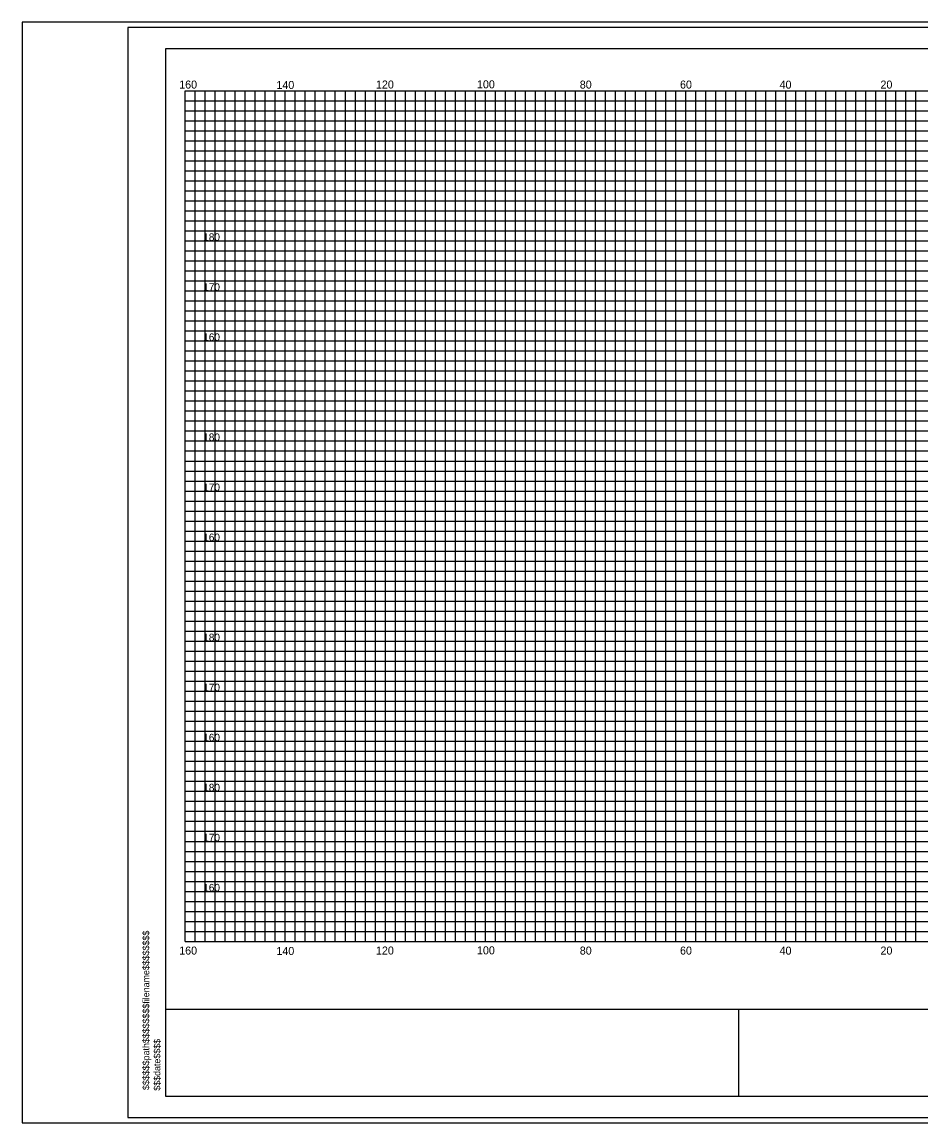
# Model space of a CAD drawing. Extents: x 967 to 1326, y 964 to 2864.
# Drawn here: x 967.4 to 1147, y 1523.7 to 1743.7 of the extents above; entities that cross this region are included whole.
import ezdxf

# ---------------------------------------------------------------- set-up
doc = ezdxf.new("R2010")
doc.units = 0
for name, color, linetype in [('Default', 7, 'Continuous'), ('RD_EX_RW', 7, 'Continuous'), ('RD_PD_Final_TX', 7, 'Continuous'), ('RD_SHT_ShtClip', 7, 'Continuous'), ('RD_XS_TX_Elev_PR', 7, 'Continuous'), ('RD_XS_TX_Slope', 7, 'Continuous')]:
    doc.layers.add(name, color=color, linetype=linetype)

msp = doc.modelspace()

# ---------------------------------------------------------------- linework, layer by layer
at = {"layer": 'RD_EX_RW'}
for p, q in [((1000, 1730), (1320, 1730)), ((1000, 1560), (1000, 1730)), ((1010, 1560), (1010, 1730)), ((1020, 1560), (1020, 1730)), ((1030, 1560), (1030, 1730)), ((1040, 1560), (1040, 1730)), ((1050, 1560), (1050, 1730)), ((1060, 1560), (1060, 1730)), ((1070, 1560), (1070, 1730)), ((1080, 1560), (1080, 1730)), ((1090, 1560), (1090, 1730)), ((1100, 1560), (1100, 1730)), ((1110, 1560), (1110, 1730)), ((1120, 1560), (1120, 1730)), ((1130, 1560), (1130, 1730)), ((1140, 1560), (1140, 1730)), ((1000, 1720), (1320, 1720)), ((1000, 1710), (1320, 1710)), ((1000, 1700), (1320, 1700)), ((1000, 1690), (1320, 1690)), ((1000, 1680), (1320, 1680)), ((1000, 1670), (1320, 1670)), ((1000, 1660), (1320, 1660)), ((1000, 1650), (1320, 1650)), ((1000, 1640), (1320, 1640)), ((1000, 1630), (1320, 1630)), ((1000, 1620), (1320, 1620)), ((1000, 1610), (1320, 1610)), ((1000, 1600), (1320, 1600)), ((1000, 1590), (1320, 1590)), ((1000, 1580), (1320, 1580)), ((1000, 1570), (1320, 1570)), ((1000, 1560), (1320, 1560))]:
    msp.add_line(p, q, dxfattribs=at)
at = {"layer": 'RD_PD_Final_TX'}
for p, q in [((996.11, 1528.98), (996.11, 1738.46)), ((996.11, 1738.46), (1323.89, 1738.46)), ((996.11, 1546.49), (1323.89, 1546.49)), ((1110.59, 1528.98), (1110.59, 1546.56)), ((1323.89, 1528.98), (996.11, 1528.98))]:
    msp.add_line(p, q, dxfattribs=at)
at = {"layer": 'RD_SHT_ShtClip'}
for p, q in [((1002, 1560), (1002, 1730)), ((1004, 1560), (1004, 1730)), ((1006, 1560), (1006, 1730)), ((1008, 1560), (1008, 1730)), ((1012, 1560), (1012, 1730)), ((1014, 1560), (1014, 1730)), ((1016, 1560), (1016, 1730)), ((1018, 1560), (1018, 1730)), ((1022, 1560), (1022, 1730)), ((1024, 1560), (1024, 1730)), ((1026, 1560), (1026, 1730)), ((1028, 1560), (1028, 1730)), ((1032, 1560), (1032, 1730)), ((1034, 1560), (1034, 1730)), ((1036, 1560), (1036, 1730)), ((1038, 1560), (1038, 1730)), ((1042, 1560), (1042, 1730)), ((1044, 1560), (1044, 1730)), ((1046, 1560), (1046, 1730)), ((1048, 1560), (1048, 1730)), ((1052, 1560), (1052, 1730)), ((1054, 1560), (1054, 1730)), ((1056, 1560), (1056, 1730)), ((1058, 1560), (1058, 1730)), ((1062, 1560), (1062, 1730)), ((1064, 1560), (1064, 1730)), ((1066, 1560), (1066, 1730)), ((1068, 1560), (1068, 1730)), ((1072, 1560), (1072, 1730)), ((1074, 1560), (1074, 1730)), ((1076, 1560), (1076, 1730)), ((1078, 1560), (1078, 1730)), ((1082, 1560), (1082, 1730)), ((1084, 1560), (1084, 1730)), ((1086, 1560), (1086, 1730)), ((1088, 1560), (1088, 1730)), ((1092, 1560), (1092, 1730)), ((1094, 1560), (1094, 1730)), ((1096, 1560), (1096, 1730)), ((1098, 1560), (1098, 1730)), ((1102, 1560), (1102, 1730)), ((1104, 1560), (1104, 1730)), ((1106, 1560), (1106, 1730)), ((1108, 1560), (1108, 1730)), ((1112, 1560), (1112, 1730)), ((1114, 1560), (1114, 1730)), ((1116, 1560), (1116, 1730)), ((1118, 1560), (1118, 1730)), ((1122, 1560), (1122, 1730)), ((1124, 1560), (1124, 1730)), ((1126, 1560), (1126, 1730)), ((1128, 1560), (1128, 1730)), ((1132, 1560), (1132, 1730)), ((1134, 1560), (1134, 1730)), ((1136, 1560), (1136, 1730)), ((1138, 1560), (1138, 1730)), ((1142, 1560), (1142, 1730)), ((1144, 1560), (1144, 1730)), ((1146, 1560), (1146, 1730)), ((1000, 1728), (1320, 1728)), ((1000, 1726), (1320, 1726)), ((1000, 1724), (1320, 1724)), ((1000, 1722), (1320, 1722)), ((1000, 1718), (1320, 1718)), ((1000, 1716), (1320, 1716)), ((1000, 1714), (1320, 1714)), ((1000, 1712), (1320, 1712)), ((1000, 1708), (1320, 1708)), ((1000, 1706), (1320, 1706)), ((1000, 1704), (1320, 1704)), ((1000, 1702), (1320, 1702)), ((1000, 1698), (1320, 1698)), ((1000, 1696), (1320, 1696)), ((1000, 1694), (1320, 1694)), ((1000, 1692), (1320, 1692)), ((1000, 1688), (1320, 1688)), ((1000, 1686), (1320, 1686)), ((1000, 1684), (1320, 1684)), ((1000, 1682), (1320, 1682)), ((1000, 1678), (1320, 1678)), ((1000, 1676), (1320, 1676)), ((1000, 1674), (1320, 1674)), ((1000, 1672), (1320, 1672)), ((1000, 1668), (1320, 1668)), ((1000, 1666), (1320, 1666)), ((1000, 1664), (1320, 1664)), ((1000, 1662), (1320, 1662)), ((1000, 1658), (1320, 1658)), ((1000, 1656), (1320, 1656)), ((1000, 1654), (1320, 1654)), ((1000, 1652), (1320, 1652)), ((1000, 1648), (1320, 1648)), ((1000, 1646), (1320, 1646)), ((1000, 1644), (1320, 1644)), ((1000, 1642), (1320, 1642)), ((1000, 1638), (1320, 1638)), ((1000, 1636), (1320, 1636)), ((1000, 1634), (1320, 1634)), ((1000, 1632), (1320, 1632)), ((1000, 1628), (1320, 1628)), ((1000, 1626), (1320, 1626)), ((1000, 1624), (1320, 1624)), ((1000, 1622), (1320, 1622)), ((1000, 1618), (1320, 1618)), ((1000, 1616), (1320, 1616)), ((1000, 1614), (1320, 1614)), ((1000, 1612), (1320, 1612)), ((1000, 1608), (1320, 1608)), ((1000, 1606), (1320, 1606)), ((1000, 1604), (1320, 1604)), ((1000, 1602), (1320, 1602)), ((1000, 1598), (1320, 1598)), ((1000, 1596), (1320, 1596)), ((1000, 1594), (1320, 1594)), ((1000, 1592), (1320, 1592)), ((1000, 1588), (1320, 1588)), ((1000, 1586), (1320, 1586)), ((1000, 1584), (1320, 1584)), ((1000, 1582), (1320, 1582)), ((1000, 1578), (1320, 1578)), ((1000, 1576), (1320, 1576)), ((1000, 1574), (1320, 1574)), ((1000, 1572), (1320, 1572)), ((1000, 1568), (1320, 1568)), ((1000, 1566), (1320, 1566)), ((1000, 1564), (1320, 1564)), ((1000, 1562), (1320, 1562))]:
    msp.add_line(p, q, dxfattribs=at)
at = {"layer": 'RD_XS_TX_Elev_PR'}
for points in [[(967.41, 1523.72), (1326.28, 1523.72), (1326.28, 1743.72), (967.41, 1743.72)], [(988.52, 1524.84), (1326.28, 1524.84), (1326.28, 1742.6), (988.52, 1742.6)]]:
    msp.add_lwpolyline(points, close=True, dxfattribs=at)

# ---------------------------------------------------------------- texts
at = {"layer": 'Default'}
for s, p in [('180', (1003.61, 1700)), ('170', (1003.61, 1690)), ('160', (1003.61, 1680)), ('180', (1003.61, 1660)), ('170', (1003.61, 1650)), ('160', (1003.61, 1640)), ('180', (1003.61, 1620)), ('170', (1003.61, 1610)), ('160', (1003.61, 1600)), ('180', (1003.61, 1590)), ('170', (1003.61, 1580)), ('160', (1003.61, 1570))]:
    msp.add_text(s, height=1.5, dxfattribs=at).set_placement(p)
for s, p in [('$$$$$$path$$$$$$$$filename$$$$$$$$', (992.83, 1530.31)), ('$$$date$$$$', (995.04, 1530.17))]:
    msp.add_text(s, height=1.3258, rotation=90, dxfattribs=at).set_placement(p)
at = {"layer": 'RD_XS_TX_Slope'}
for s, p in [('160', (998.81, 1730.42)), ('140', (1018.23, 1730.34)), ('120', (1038.12, 1730.43)), ('100', (1058.3, 1730.47)), ('80', (1078.84, 1730.42)), ('60', (1098.86, 1730.42)), ('40', (1118.75, 1730.41)), ('20', (1138.91, 1730.42)), ('160', (998.81, 1557.37)), ('140', (1018.23, 1557.29)), ('120', (1038.12, 1557.38)), ('100', (1058.3, 1557.42)), ('80', (1078.84, 1557.37)), ('60', (1098.86, 1557.37)), ('40', (1118.75, 1557.36)), ('20', (1138.91, 1557.37))]:
    msp.add_text(s, height=1.6, dxfattribs=at).set_placement(p)

doc.saveas('drawing.dxf')
